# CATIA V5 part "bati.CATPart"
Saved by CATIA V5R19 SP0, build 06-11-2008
Part number: Part3
Bounding box of the stored display mesh (mm): x -90 to 90, y -37 to 263, z -66.8 to 14.996
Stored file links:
  D:\thinkmotion-MPB\Dropbox\CIAO82010_JCF\BAUVIN\554_bauvin\bati.CATPart
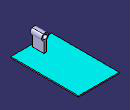
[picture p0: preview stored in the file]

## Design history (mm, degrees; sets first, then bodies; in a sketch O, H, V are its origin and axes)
Body1 (main body)
  Sketch1 on yz-plane, origin (0, 0, 0), H (0, 1, 0), V (0, 0, 1)
    point P1 (-25, 0)
    line L1 (-25, 0) -> (25, 0)
    line L2 (25, 0) -> (25, 15)
    line L3 (25, 15) -> (-25, 15)
    line L4 (-25, 15) -> (-25, 0)
    length L2 = 15
    length L3 = 50
    coincidence: P1 H
    horizontal: L1 H, L3 H
    vertical: L2 V, L4 V
    symmetry: L4 L2 V
  Shaft1: profile Sketch1, axis Sketch1.L1, angle 360
  Sketch2 on yz-plane, origin (0, 0, 0), H (0, 1, 0), V (0, 0, 1)
    line L1 (-25, 0) -> (25, 0)
    line L2 (25, 0) -> (25, -61.8)
    line L3 (25, -61.8) -> (-25, -61.8)
    line L4 (-25, -61.8) -> (-25, 0)
    reference projected line E1 (-25, 15) -> (-25, -15) from edge [face of Shaft1 from Sketch1.L4 | face of Shaft1 from Sketch1.L3]
    reference projected line E2 (25, 15) -> (25, -15) from edge [face of Shaft1 from Sketch1.L3 | face of Shaft1 from Sketch1.L2]
    length L4 = 61.8
    horizontal: L1 H, L3 H
    vertical: L2 V, L4 V
    coincidence: L1 H, L4 E1, L2 E2
  Pad1: profile Sketch2, direction (1, 0, 0), length 5, mirrored extent
  Sketch3 on face of Pad1 from Sketch2.L3, origin (0, 0, -61.8), H (1, 0, 0), V (0, -1, 0)
    line L1 (-90, 37) -> (90, 37)
    line L2 (90, 37) -> (90, -263)
    line L3 (90, -263) -> (-90, -263)
    line L4 (-90, -263) -> (-90, 37)
    reference projected line E1 (-5, 25) -> (5, 25) from edge [face of Pad1 from Sketch2.L3 | face of Pad1 from Sketch2.L4]
    distance L1 L3 = 300
    distance E1 L1 = 12
    length L3 = 180
    horizontal: L1 H, L3 H
    vertical: L2 V, L4 V
    symmetry: L4 L2 V
  Pad2: profile Sketch3, direction (0, 0, -1), length 5
  Sketch4 on face of Shaft1 from Sketch1.L4, origin (0, -25, 0), H (1, 0, 0), V (0, 0, 1)
    circle A1 centre (0, 0) radius 10
    radius A1 = 10
  Pocket1: profile Sketch4, direction (0, 1, 0), through (limit type 3)
  Point1: type Center, Curve edge [face of Shaft1 from Sketch1.L2 | face of Pocket1 from Sketch4.A1]
  Line1: type Normal, RefPoint Point1, RefSkin face of Shaft1 from Sketch1.L2, Start 0, End 20
  Point2: type Center, Curve edge of Pocket1
  Sketch5 on end face of Pad2, origin (0, 0, -66.8), H (1, 0, 0), V (0, -1, 0)
    circle A1 centre (0, -230.7495) radius 5
    point P1 (0, -230.7495)
    radius A1 = 5
    coincidence: P1 V
  Sketch6 on start face of Pad2, origin (0, 0, -61.8), H (1, 0, 0), V (0, 1, 0)
    circle A1 centre (0, 230.3847) radius 5
    point P1 (0, 230.3847)
    radius A1 = 5
    coincidence: P1 V
  Sketch7 on end face of Pad2, origin (0, 0, -66.8), H (1, 0, 0), V (0, -1, 0)
    circle A1 centre (0, -200.6321) radius 7.7794
    point P1 (0, -200.6321)
    coincidence: P1 V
